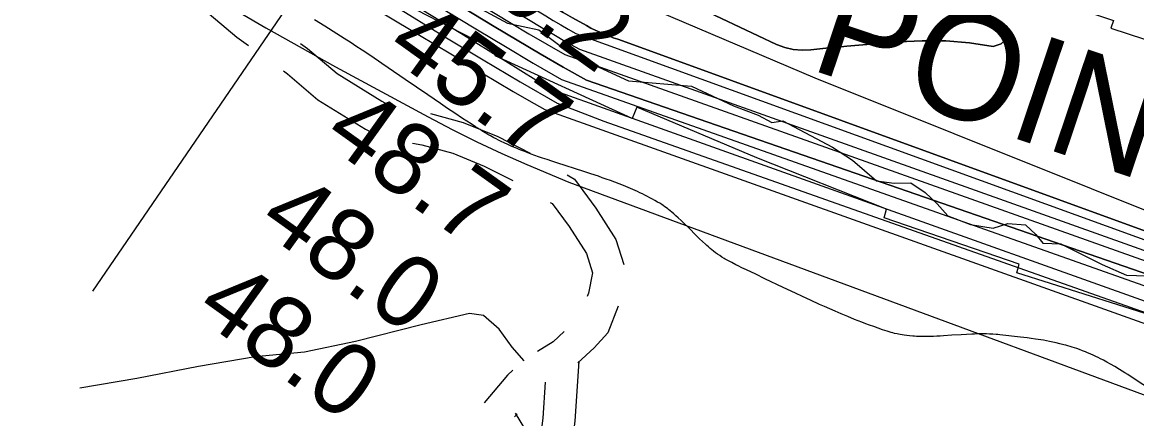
# Model space of a CAD drawing. Extents: x 3161615 to 3199515, y 867541 to 892976.
# Drawn here: x 3182695 to 3183730, y 878242 to 878610 of the extents above; entities that cross this region are included whole.
import ezdxf

# ---------------------------------------------------------------- set-up
doc = ezdxf.new("R2010")
doc.units = 0
for name, color, linetype in [('V-RIVR-EDGE', 7, 'Continuous'), ('V-RIVR-RANG', 7, 'Continuous'), ('V-ROAD-CNTR', 7, 'Continuous'), ('V-RRAP-RVMT', 7, 'Continuous'), ('V-RRAP-RVMT-IDEN', 7, 'Continuous'), ('V-TOPO-DPTH', 7, 'Continuous'), ('V-TOPO-MAJR', 7, 'Continuous'), ('V-TOPO-MINR', 7, 'Continuous'), ('V-TOPO-WATR', 7, 'Continuous')]:
    doc.layers.add(name, color=color, linetype=linetype)

msp = doc.modelspace()

# ---------------------------------------------------------------- linework, layer by layer
at = {"layer": 'V-RIVR-EDGE'}
msp.add_lwpolyline([(3183117.6, 878624.9), (3183145.7, 878609.6), (3183174.8, 878603.3), (3183206.6, 878579.9), (3183258.1, 878555.9), (3183316.7, 878551), (3183355.8, 878532.8), (3183378.7, 878524.1), (3183391.5, 878517.4), (3183401.5, 878518.8), (3183447.7, 878494.4), (3183466.3, 878482.4), (3183488.7, 878463.3), (3183504.9, 878460.9), (3183520.6, 878461.3), (3183533.9, 878452.2), (3183544.9, 878441.7), (3183554.9, 878430.7), (3183575.8, 878422.6), (3183596.8, 878419.2), (3183610.6, 878423.4), (3183626.9, 878422.4), (3183636.4, 878413.3), (3183643, 878405.2), (3183659.7, 878404.7), (3183698.3, 878385.5), (3183720.7, 878375.5), (3183739.3, 878374.9)], dxfattribs=at)
at = {"layer": 'V-RIVR-RANG'}
msp.add_line((3182760.7, 878360.6), (3184853.5, 881422.8), dxfattribs=at)
at = {"layer": 'V-ROAD-CNTR'}
for points in [[(3182826.8, 878650.5), (3182859, 878626.7), (3182894.6, 878596.5), (3182905.3, 878588.8)], [(3183142.7, 878498.5), (3183139.9, 878499.8), (3183137.4, 878501.1), (3183135.2, 878502.2), (3183133.3, 878503.2), (3183130, 878505), (3183127.6, 878506.3), (3183125.7, 878507.4), (3183123, 878509), (3183120.4, 878510.7), (3183116.1, 878513.4), (3183112.1, 878516), (3183104.2, 878521.1), (3183096.9, 878525.9), (3183090, 878530.5), (3183083.6, 878534.9), (3183071.7, 878543), (3183050.8, 878557.4), (3183035.1, 878568.2), (3183029.2, 878572.2), (3183018.8, 878579.2), (3183011, 878584.4), (3183005.1, 878588.3), (3183000.7, 878591.2), (3182994.1, 878595.4), (3182987.4, 878599.7), (3182976.2, 878606.7), (3182966.5, 878612.8)], [(3182953.7, 878590.8), (3182960.1, 878586), (3182987.5, 878562.8), (3183029, 878537.2), (3183035.3, 878533.8)], [(3182937.7, 878565.4), (3182941.4, 878562.5), (3182969.8, 878538.5), (3183014.1, 878511.1), (3183019.3, 878508.3)], [(3183074.3, 878525.6), (3183104.8, 878517.4), (3183136.8, 878504.2), (3183166.9, 878488.8)], [(3183057.7, 878498.3), (3183066.2, 878496.7), (3183095.2, 878488.9), (3183124.3, 878476.9), (3183150.9, 878463.4)], [(3183475, 878331.9), (3183471.5, 878333.2), (3183468.2, 878334.5), (3183461.8, 878337.1), (3183455.8, 878339.6), (3183450.3, 878342), (3183445.1, 878344.3), (3183440.2, 878346.4), (3183435.6, 878348.4), (3183427.2, 878352.3), (3183419.7, 878355.8), (3183413.3, 878358.8), (3183402, 878364.2), (3183385, 878372.3), (3183376.5, 878376.4), (3183367.9, 878380.4), (3183363.5, 878382.5), (3183360.2, 878384.1), (3183357.8, 878385.3), (3183354.1, 878387.2), (3183350.4, 878389.1), (3183349.3, 878389.7), (3183348.1, 878390.3), (3183347, 878391), (3183344.9, 878392.3), (3183342.9, 878393.7), (3183340.9, 878395), (3183339.1, 878396.4), (3183337.3, 878397.7), (3183335.6, 878399.1), (3183334, 878400.4), (3183332.5, 878401.8), (3183331, 878403.1), (3183329.6, 878404.3), (3183326.9, 878406.9), (3183324.3, 878409.3), (3183322, 878411.6), (3183313.3, 878420.3), (3183310, 878423.5), (3183307.1, 878426.3), (3183304.5, 878428.7), (3183302.3, 878430.8), (3183300.3, 878432.6), (3183298.5, 878434.1), (3183296.9, 878435.4), (3183295.5, 878436.5), (3183294.3, 878437.4), (3183292.1, 878439.1), (3183290.4, 878440.2), (3183289.1, 878441.1), (3183287.2, 878442.3), (3183285.2, 878443.5), (3183282.8, 878444.9), (3183280.5, 878446.2), (3183278.1, 878447.5), (3183275.8, 878448.7), (3183273.5, 878449.9), (3183271.2, 878451), (3183268.9, 878452.1), (3183266.6, 878453.2), (3183264.4, 878454.2), (3183262.2, 878455.2), (3183257.9, 878457), (3183253.6, 878458.8), (3183249.5, 878460.4), (3183245.4, 878462), (3183241.5, 878463.4), (3183237.6, 878464.8), (3183233.9, 878466.1), (3183230.3, 878467.4), (3183223.2, 878469.7), (3183216.6, 878471.9), (3183191.6, 878479.9), (3183187, 878481.4), (3183182.6, 878482.9), (3183178.5, 878484.2), (3183174.7, 878485.6), (3183171.2, 878486.8), (3183167.8, 878488), (3183164.7, 878489.2), (3183161.8, 878490.3), (3183159.1, 878491.4), (3183156.6, 878492.4), (3183154.2, 878493.4), (3183149.9, 878495.2), (3183146, 878496.9), (3183142.7, 878498.5)], [(3183201.4, 878468.6), (3183208, 878464.6), (3183227.8, 878437.8), (3183246.5, 878408.6), (3183253.9, 878385.5)], [(3183185.4, 878443.2), (3183187.4, 878442), (3183203.1, 878420.8), (3183219.1, 878395.8), (3183224.8, 878377.8), (3183221.1, 878359), (3183219.9, 878355.8)], [(3183248.5, 878346.7), (3183239.1, 878322.1), (3183226.4, 878308.1), (3183211.3, 878294.2)], [(3183161.4, 878296.1), (3183150.2, 878308.8), (3183138, 878325.3), (3183123.4, 878338.2), (3183110.7, 878340), (3183065.8, 878329.5), (3183004.8, 878314.1), (3182957.4, 878304.2), (3182911.6, 878299.7), (3182858.8, 878290.7), (3182801.7, 878279.7), (3182748.7, 878270.6)], [(3183744, 878268.9), (3183727.9, 878279.4), (3183721.9, 878283.3), (3183719.2, 878284.9), (3183716.7, 878286.5), (3183714.3, 878287.9), (3183709.9, 878290.6), (3183705.9, 878292.9), (3183702.5, 878294.8), (3183699.4, 878296.5), (3183696.7, 878297.9), (3183694.3, 878299.1), (3183692.2, 878300.1), (3183690.3, 878300.9), (3183687.1, 878302.4), (3183684.6, 878303.5), (3183682.7, 878304.3), (3183679.9, 878305.4), (3183677, 878306.5), (3183674.7, 878307.3), (3183672.6, 878308.1), (3183670.4, 878308.7), (3183668.4, 878309.4), (3183666.4, 878310), (3183664.4, 878310.5), (3183662.5, 878311), (3183658.9, 878311.9), (3183655.4, 878312.7), (3183652.2, 878313.4), (3183649.1, 878314.1), (3183646.3, 878314.6), (3183643.6, 878315.1), (3183641.1, 878315.5), (3183636.3, 878316.2), (3183632.2, 878316.8), (3183628.5, 878317.3), (3183622.2, 878318.1), (3183603.1, 878320.2), (3183601.4, 878320.4), (3183599.8, 878320.6), (3183596.7, 878320.8), (3183593.6, 878320.9), (3183590.6, 878321), (3183587.7, 878321.1), (3183584.9, 878321.1), (3183582.2, 878321), (3183579.5, 878320.9), (3183577, 878320.8), (3183572, 878320.6), (3183567.3, 878320.3), (3183558.6, 878319.7), (3183550.9, 878319.2), (3183547.6, 878319), (3183544.5, 878318.8), (3183541.5, 878318.7), (3183538.8, 878318.6), (3183536.2, 878318.6), (3183533.8, 878318.6), (3183531.6, 878318.6), (3183529.4, 878318.6), (3183527.5, 878318.7), (3183525.6, 878318.7), (3183523.9, 878318.8), (3183522.3, 878319), (3183519.3, 878319.2), (3183516.6, 878319.5), (3183514.3, 878319.8), (3183512.3, 878320.1), (3183510.5, 878320.4), (3183509, 878320.7), (3183507.7, 878321), (3183505.3, 878321.5), (3183503.6, 878321.9), (3183502.3, 878322.3), (3183500.3, 878322.9), (3183498.4, 878323.5), (3183494.1, 878324.9), (3183490, 878326.3), (3183486, 878327.8), (3183482.2, 878329.2), (3183478.5, 878330.5), (3183475, 878331.9)], [(3183198.4, 878323.1), (3183188.3, 878313.8), (3183173.8, 878304.8)], [(3183212, 878295.8), (3183208.5, 878240), (3183203.5, 878201.4)], [(3183150.9, 878287.2), (3183145.8, 878282.6), (3183124.3, 878257.1)], [(3183180.7, 878276.1), (3183178.7, 878242.9), (3183174.8, 878213.5)], [(3183152.9, 878247.3), (3183166.9, 878224.6), (3183176.1, 878213.5)], [(3183154.9, 878246.8), (3183152.4, 878243.9)]]:
    msp.add_lwpolyline(points, dxfattribs=at)
at = {"layer": 'V-RRAP-RVMT'}
for points in [[(3182576.9, 879156.3), (3182585.4, 879168.9), (3182687.6, 879097), (3182703.9, 879120.1), (3182808, 879050.1), (3182809.8, 879052.4), (3182915, 878984.7), (3182918.2, 878990.3), (3183053.2, 878911.1), (3183050.1, 878904.6), (3183141.4, 878854.1), (3183251.4, 878798.3), (3183250.1, 878795), (3183348.3, 878749.2), (3183353.4, 878760.4), (3183590.9, 878661), (3183588.6, 878652.6), (3183708.6, 878612.1), (3183706.1, 878604.9), (3183832.3, 878563.9)], [(3183743.9, 878338.1), (3183619, 878377.8), (3183621.2, 878385.7), (3183495.8, 878428.7), (3183498, 878436.9), (3183377.4, 878484.4), (3183266.1, 878531.6), (3183261.5, 878521), (3183134.5, 878579.3), (3183136.3, 878583.3), (3183018.2, 878644.4), (3183019.3, 878646.9), (3182903.2, 878711.2), (3182905.7, 878715.5), (3182807.8, 878772.9), (3182804, 878766.4), (3182686, 878843.5), (3182681.7, 878838.1), (3182573.6, 878909.9), (3182561.9, 878892.7), (3182455.5, 878967), (3182444.7, 878952.8)]]:
    msp.add_lwpolyline(points, dxfattribs=at)
at = {"layer": 'V-TOPO-DPTH'}
for points in [[(3184008.2, 878283.6), (3183219.1, 878556.6), (3183197.5, 878568.8), (3183176.1, 878581.2), (3183154.8, 878593.8), (3183133.6, 878606.5), (3182990.9, 878693.1), (3182898.9, 878750), (3182807.6, 878808), (3182717.3, 878867.5), (3182627.7, 878928.1), (3182398.4, 879086.1), (3182385.8, 879095.1), (3182373.5, 879104.5), (3182361.6, 879114.3), (3182349.9, 879124.4), (3181936.3, 879498.8)], [(3182122.6, 879347), (3182207.7, 879268), (3182364.5, 879125.5), (3182372.2, 879118.8), (3182380, 879112.4), (3182388.1, 879106.2), (3182396.4, 879100.3), (3182521.7, 879014), (3182593.1, 878965.7), (3182665.1, 878918.3), (3182737.9, 878872.2), (3182811.3, 878826.9), (3183165.2, 878613), (3183177, 878605.9), (3183188.8, 878599), (3183200.7, 878592.1), (3183212.7, 878585.4), (3184037, 878291.6)], [(3182122.6, 879347), (3182207.7, 879268), (3182364.5, 879125.5), (3182372.2, 879118.8), (3182380, 879112.4), (3182388.1, 879106.2), (3182396.4, 879100.3), (3182521.7, 879014), (3182593.1, 878965.7), (3182665.1, 878918.3), (3182737.9, 878872.2), (3182811.3, 878826.9), (3183165.2, 878613), (3183177, 878605.9), (3183188.8, 878599), (3183200.7, 878592.1), (3183212.7, 878585.4), (3184037, 878291.6)], [(3182593.4, 878983.5), (3183197.5, 878619.6), (3183201.8, 878617.1), (3183206.1, 878614.6), (3183219.3, 878607.3), (3183223.3, 878605.1), (3183227.4, 878603.1), (3183231.5, 878601.2), (3183235.7, 878599.4), (3183239.9, 878597.7), (3183244.1, 878596.1), (3183248.4, 878594.6), (3183252.7, 878593.2), (3184062.5, 878298.5)], [(3184062.5, 878298.5), (3183252.7, 878593.2), (3183248.4, 878594.6), (3183244.1, 878596.1), (3183239.9, 878597.7), (3183235.7, 878599.4), (3183231.5, 878601.2), (3183227.4, 878603.1), (3183223.3, 878605.1), (3183219.3, 878607.3), (3183206.1, 878614.6), (3183201.8, 878617.1), (3183197.5, 878619.6), (3182593.4, 878983.5)], [(3183221.2, 878915.7), (3183218, 878917.3), (3183203, 878873.2), (3183207.9, 878870.9), (3183338.5, 878810.2), (3183351.7, 878800.8), (3183364.8, 878791.1), (3183608.4, 878599.8), (3183608.5, 878594.1)], [(3183608.5, 878594.1), (3183608.4, 878599.8), (3183364.8, 878791.1)], [(3183608.5, 878594.1), (3183604.2, 878590.4), (3183596.9, 878588), (3183575, 878591.2), (3183553.1, 878593.1), (3183531.1, 878593.3), (3183509.1, 878592.3), (3183461, 878588.1), (3183452.6, 878587.4), (3183444.3, 878586.6), (3183436, 878585.7), (3183427.6, 878584.7), (3183419.4, 878584.4), (3183411.3, 878585.1), (3183403.5, 878587), (3183395.8, 878589.9), (3183276.4, 878646.4)], [(3183276.4, 878646.4), (3183395.8, 878589.9), (3183403.5, 878587), (3183411.3, 878585.1), (3183419.4, 878584.4), (3183427.6, 878584.7), (3183436, 878585.7), (3183444.3, 878586.6), (3183452.6, 878587.4), (3183461, 878588.1), (3183509.1, 878592.3), (3183531.1, 878593.3), (3183553.1, 878593.1), (3183575, 878591.2), (3183596.9, 878588), (3183604.2, 878590.4), (3183608.5, 878594.1)]]:
    msp.add_lwpolyline(points, dxfattribs=at)
at = {"layer": 'V-TOPO-MAJR'}
msp.add_lwpolyline([(3181603.1, 879751.3), (3182052.8, 879323.8), (3182100.3, 879280.1), (3182148.7, 879237.4), (3182198.4, 879196.3), (3182249, 879156.3), (3182300.4, 879117), (3182326.2, 879097.7), (3182352.3, 879078.7), (3182378.7, 879060.4), (3182405.5, 879042.4), (3182954.4, 878681.4), (3182987.8, 878659.7), (3183021.4, 878638.2), (3183055.1, 878617), (3183089.1, 878596.1), (3183123.2, 878575.5), (3183157.5, 878555.1), (3183192, 878535.2), (3183235.3, 878518.6), (3184012.5, 878244)], dxfattribs=at)
at = {"layer": 'V-TOPO-MINR'}
for points in [[(3181661.9, 879726.5), (3182335.2, 879123.2), (3182350.9, 879109.7), (3182367, 879096.5), (3182383.5, 879084), (3182400.4, 879071.9), (3182845.8, 878764.9), (3182897.7, 878729.7), (3182950, 878695.2), (3183002.9, 878661.5), (3183056.2, 878628.5), (3183102.6, 878600.2), (3183186.2, 878548.4), (3184038.5, 878244.3)], [(3181770.3, 879640.8), (3182342.6, 879123.9), (3182356.3, 879112), (3182370.3, 879100.5), (3182384.7, 879089.6), (3182399.4, 879079), (3182736.5, 878846.7), (3182807.3, 878798.8), (3182878.6, 878751.7), (3182950.8, 878705.8), (3183023.4, 878660.8), (3183118, 878603.3), (3183143.9, 878587.8), (3183169.8, 878572.4), (3183196, 878557.3), (3184018.6, 878266.4)], [(3181936.3, 879498.8), (3182349.9, 879124.4), (3182361.6, 879114.3), (3182373.5, 879104.5), (3182385.8, 879095.1), (3182398.4, 879086.1), (3182627.7, 878928.1), (3182717.3, 878867.5), (3182807.6, 878808), (3182898.9, 878750), (3182990.9, 878693.1), (3183133.6, 878606.5), (3183154.8, 878593.8), (3183176.1, 878581.2), (3183197.5, 878568.8), (3183219.1, 878556.6), (3184008.2, 878283.6)], [(3181822, 879407.7), (3181898.5, 879338.6), (3181976.2, 879270.8), (3182055.3, 879204.7), (3182135.5, 879139.8), (3182258.4, 879042.8), (3182278.1, 879027.6), (3182298, 879012.8), (3182318.3, 878998.4), (3182338.8, 878984.4), (3182731.6, 878722.5), (3182794, 878682.1), (3182857.2, 878642.9), (3182921.3, 878605.4), (3182986.2, 878569.1), (3183072.1, 878522.5), (3183094.6, 878510.7), (3183117.4, 878499.3), (3183140.6, 878488.6), (3183163.9, 878478.3), (3183202.7, 878461.8), (3184028.5, 878156.7)], [(3182094, 879363.6), (3182357.2, 879125), (3182366.9, 879116.6), (3182376.8, 879108.4), (3182387, 879100.7), (3182397.4, 879093.2), (3182555.5, 878984.3), (3182645.6, 878923.4), (3182736.4, 878863.5), (3182828.3, 878805.3), (3182920.8, 878748.1), (3183149.3, 878609.7), (3183165.8, 878599.8), (3183182.4, 878590), (3183199.1, 878580.4), (3184023, 878287.7)], [(3182135.4, 879345.2), (3182196.3, 879286.9), (3182258.1, 879229.5), (3182371.8, 879126.1), (3182377.5, 879121.1), (3182383.3, 879116.3), (3182389.3, 879111.7), (3182395.4, 879107.3), (3182488, 879043.6), (3182540.8, 879007.9), (3182594.1, 878972.9), (3182647.9, 878938.8), (3182702.2, 878905.4), (3183181.3, 878616.3), (3183188.3, 878612.1), (3183195.3, 878608), (3183202.3, 878604), (3183209.4, 878600), (3184050.2, 878295.2)], [(3182593.4, 878983.5), (3183197.5, 878619.6), (3183201.8, 878617.1), (3183206.1, 878614.6), (3183219.3, 878607.3), (3183223.3, 878605.1), (3183227.4, 878603.1), (3183231.5, 878601.2), (3183235.7, 878599.4), (3183239.9, 878597.7), (3183244.1, 878596.1), (3183248.4, 878594.6), (3183252.7, 878593.2), (3184062.5, 878298.5)], [(3182646.4, 878967.4), (3182711.5, 878930.2), (3182776.9, 878893.7), (3182842.6, 878857.6), (3182940.9, 878804.4), (3182988, 878778.6), (3183035.1, 878752.8), (3183082.1, 878726.7), (3183129, 878700.5), (3183163.5, 878681.1), (3183193.3, 878664.9), (3183223.4, 878649.4), (3183254.1, 878635), (3183285, 878621.1), (3183431.2, 878558.7), (3184073.8, 878301.5)], [(3182633, 878850), (3182710.4, 878806.4), (3182787.6, 878762.3), (3182864.3, 878717.6), (3182940.8, 878672.4), (3183064.2, 878598.6), (3183078.7, 878589.9), (3183093.2, 878581.2), (3183107.7, 878572.4), (3183122.1, 878563.6), (3183136.6, 878554.9), (3183151.2, 878546.2), (3183165.8, 878537.7), (3183180.5, 878529.3), (3183995.5, 878238.6)], [(3183608.5, 878594.1), (3183608.4, 878599.8), (3183364.8, 878791.1)], [(3183276.4, 878646.4), (3183395.8, 878589.9), (3183403.5, 878587), (3183411.3, 878585.1), (3183419.4, 878584.4), (3183427.6, 878584.7), (3183436, 878585.7), (3183444.3, 878586.6), (3183452.6, 878587.4), (3183461, 878588.1), (3183509.1, 878592.3), (3183531.1, 878593.3), (3183553.1, 878593.1), (3183575, 878591.2), (3183596.9, 878588), (3183604.2, 878590.4), (3183608.5, 878594.1)]]:
    msp.add_lwpolyline(points, dxfattribs=at)
at = {"layer": 'V-TOPO-WATR'}
msp.add_lwpolyline([(3182122.6, 879347), (3182207.7, 879268), (3182364.5, 879125.5), (3182372.2, 879118.8), (3182380, 879112.4), (3182388.1, 879106.2), (3182396.4, 879100.3), (3182521.7, 879014), (3182593.1, 878965.7), (3182665.1, 878918.3), (3182737.9, 878872.2), (3182811.3, 878826.9), (3183165.2, 878613), (3183177, 878605.9), (3183188.8, 878599), (3183200.7, 878592.1), (3183212.7, 878585.4), (3184037, 878291.6)], dxfattribs=at)

# ---------------------------------------------------------------- texts
at = {"layer": 'V-RIVR-RANG'}
for s, rotation, p in [('-0.2', 324.305, (3183104.8, 878651.6)), ('45.7', 324.3483, (3183030.6, 878581.7)), ('48.7', 324.3483, (3182972.5, 878500.3)), ('48.0', 324.3483, (3182912, 878420.6)), ('48.0', 324.3483, (3182853.9, 878339.2))]:
    msp.add_text(s, height=67, rotation=rotation, dxfattribs=at).set_placement(p)
at = {"layer": 'V-RRAP-RVMT-IDEN'}
msp.add_text('POINT', height=100, rotation=341.3901, dxfattribs=at).set_placement((3183424.5, 878567.5))

doc.saveas('drawing.dxf')
